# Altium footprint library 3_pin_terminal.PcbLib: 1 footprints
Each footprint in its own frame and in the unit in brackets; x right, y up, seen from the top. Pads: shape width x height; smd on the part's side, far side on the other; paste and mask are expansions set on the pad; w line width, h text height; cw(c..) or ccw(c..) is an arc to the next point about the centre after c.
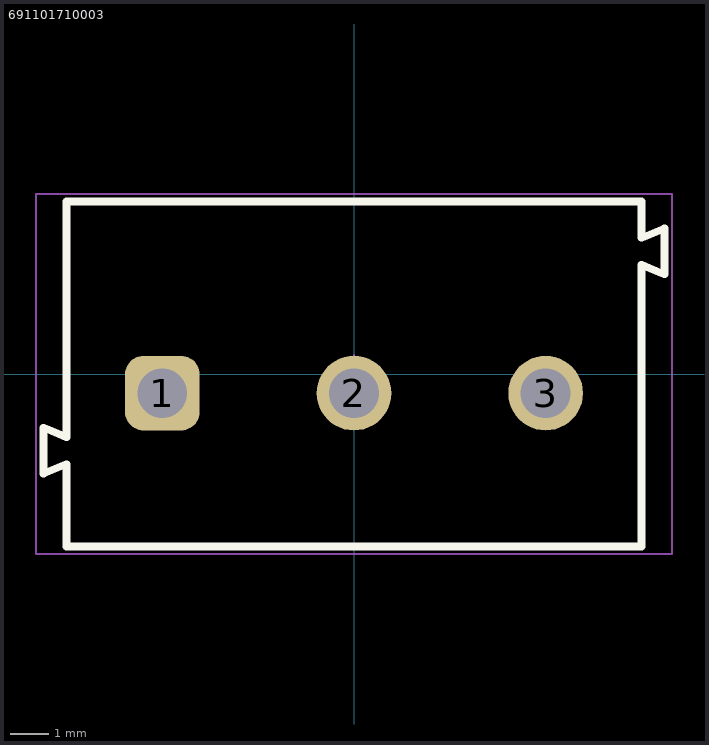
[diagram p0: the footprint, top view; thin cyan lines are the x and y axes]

## 691101710003 [mm] "5,00mm - modular - blue - Horizontal entry with pressure clamp - 12,6mm height - 03p"
height 12.6
pads (3):
  rrect50% 1.95x1.95 hole 1.3: 1(-5,-0.5)
  round 1.95 hole 1.3: 2(0,-0.5) 3(5,-0.5)
Top Overlay:
  lines w0.2: -7.5,-2.35 -8.1,-2.6 -8.1,-1.4 -7.5,-1.65 -7.5,4.5 7.5,4.5 7.5,3.55 8.1,3.8 8.1,2.6 7.5,2.85 7.5,-4.5 -7.5,-4.5 -7.5,-2.35
Top Designator:
  text ".Designator" at -7.498,-0.5 h1.5
Top Component Outline:
  lines w0.1: -7.5,-2.35 -8.1,-2.6 -8.1,-1.4 -7.5,-1.65 -7.5,4.5 7.5,4.5 7.5,3.55 8.1,3.8 8.1,2.6 7.5,2.85 7.5,-4.5 -7.5,-4.5 -7.5,-2.35
Top 3D Body:
  lines w0.1: -7.5,-2.35 -8.1,-2.6 -8.1,-1.4 -7.5,-1.65 -7.5,4.5 7.5,4.5 7.5,3.55 8.1,3.8 8.1,2.6 7.5,2.85 7.5,-4.5 -7.5,-4.5 -7.5,-2.35
Top Courtyard:
  lines w0.05: -8.3,-4.7 8.3,-4.7 8.3,4.7 -8.3,4.7 -8.3,-4.7
Top Component Center:
  lines w0.05: -0.5,0 0.5,0 ; 0,-0.5 0,0.5
3D body "691101710003.stp": height 12.65, standoff -3.75, extent -8.1,-4.5 8.1,4.5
